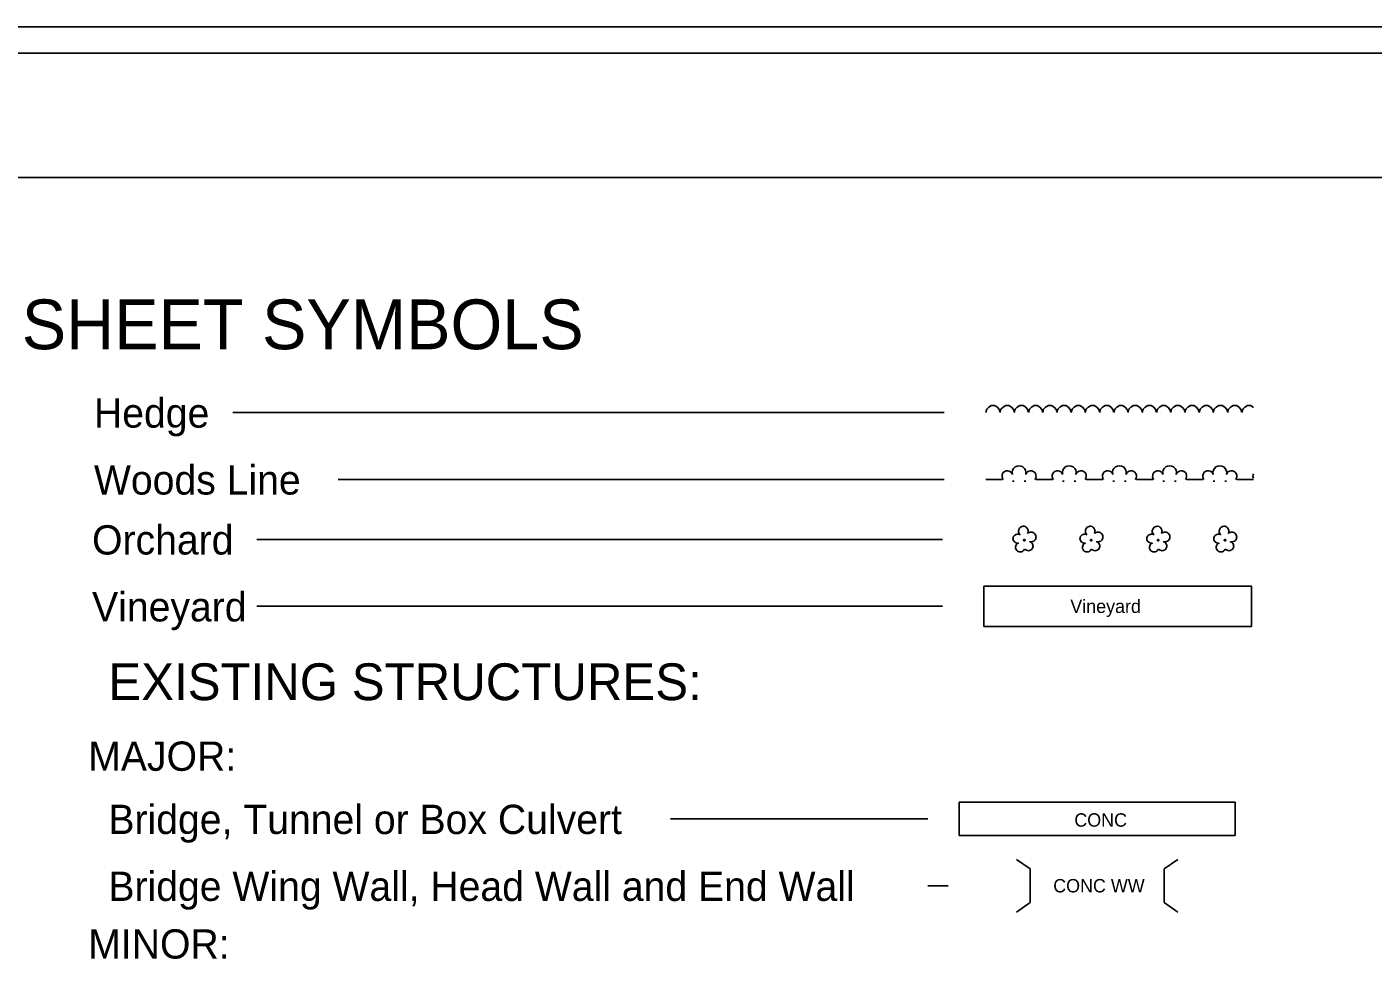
# Model space of a CAD drawing. Extents: x 811137 to 813186, y 647386 to 648494.
# Drawn here: x 812004.1 to 812410, y 648210.2 to 648494 of the extents above; entities that cross this region are included whole.
import ezdxf

# ---------------------------------------------------------------- set-up
doc = ezdxf.new("R2010")
doc.units = 0
for name, color, linetype in [('Default', 7, 'Continuous'), ('Sheet_Plan', 7, 'Continuous'), ('Sheet_Symbology', 7, 'Continuous'), ('z - Construction', 7, 'Continuous')]:
    doc.layers.add(name, color=color, linetype=linetype)

msp = doc.modelspace()

# ---------------------------------------------------------------- linework, layer by layer
at = {"layer": 'Default'}
msp.add_lwpolyline([(812820.63, 648494.02), (811136.63, 648494.02), (811136.63, 647394.02), (812820.63, 647394.02)], close=True, dxfattribs=at)
at = {"layer": 'Sheet_Plan'}
msp.add_line((812803.27, 648448.58), (811178.27, 648448.58), dxfattribs=at)
at = {"layer": 'Sheet_Symbology'}
for p, q in [((812293.25, 648377.76), (812293.56, 648378.72)), ((812293.56, 648378.72), (812294.16, 648379.37)), ((812294.16, 648379.37), (812294.97, 648379.83)), ((812294.97, 648379.83), (812295.93, 648379.83)), ((812295.93, 648379.83), (812296.74, 648379.32)), ((812296.74, 648379.32), (812297.29, 648378.67)), ((812297.29, 648378.67), (812297.49, 648377.81)), ((812297.54, 648377.76), (812297.84, 648378.72)), ((812297.84, 648378.72), (812298.45, 648379.37)), ((812298.45, 648379.37), (812299.26, 648379.83)), ((812299.26, 648379.83), (812300.22, 648379.83)), ((812300.22, 648379.83), (812301.02, 648379.32)), ((812301.02, 648379.32), (812301.58, 648378.67)), ((812301.58, 648378.67), (812301.78, 648377.81)), ((812301.83, 648377.76), (812302.13, 648378.72)), ((812302.13, 648378.72), (812302.74, 648379.37)), ((812302.74, 648379.37), (812303.55, 648379.83)), ((812303.55, 648379.83), (812304.5, 648379.83)), ((812304.5, 648379.83), (812305.31, 648379.32)), ((812305.31, 648379.32), (812305.87, 648378.67)), ((812305.87, 648378.67), (812306.07, 648377.81)), ((812306.12, 648377.76), (812306.42, 648378.72)), ((812306.42, 648378.72), (812307.03, 648379.37)), ((812307.03, 648379.37), (812307.83, 648379.83)), ((812307.83, 648379.83), (812308.79, 648379.83)), ((812308.79, 648379.83), (812309.6, 648379.32)), ((812309.6, 648379.32), (812310.15, 648378.67)), ((812310.15, 648378.67), (812310.36, 648377.81)), ((812310.41, 648377.76), (812310.71, 648378.72)), ((812310.71, 648378.72), (812311.31, 648379.37)), ((812311.31, 648379.37), (812312.12, 648379.83)), ((812312.12, 648379.83), (812313.08, 648379.83)), ((812313.08, 648379.83), (812313.89, 648379.32)), ((812313.89, 648379.32), (812314.44, 648378.67)), ((812314.44, 648378.67), (812314.64, 648377.81)), ((812314.69, 648377.76), (812315, 648378.72)), ((812315, 648378.72), (812315.6, 648379.37)), ((812315.6, 648379.37), (812316.41, 648379.83)), ((812316.41, 648379.83), (812317.37, 648379.83)), ((812317.37, 648379.83), (812318.17, 648379.32)), ((812318.17, 648379.32), (812318.73, 648378.67)), ((812318.73, 648378.67), (812318.93, 648377.81)), ((812318.98, 648377.76), (812319.28, 648378.72)), ((812319.28, 648378.72), (812319.89, 648379.37)), ((812319.89, 648379.37), (812320.7, 648379.83)), ((812320.7, 648379.83), (812321.66, 648379.83)), ((812321.66, 648379.83), (812322.46, 648379.32)), ((812322.46, 648379.32), (812323.02, 648378.67)), ((812323.02, 648378.67), (812323.22, 648377.81)), ((812323.27, 648377.76), (812323.57, 648378.72)), ((812323.57, 648378.72), (812324.18, 648379.37)), ((812324.18, 648379.37), (812324.99, 648379.83)), ((812324.99, 648379.83), (812325.94, 648379.83)), ((812325.94, 648379.83), (812326.75, 648379.32)), ((812326.75, 648379.32), (812327.31, 648378.67)), ((812327.31, 648378.67), (812327.51, 648377.81)), ((812327.56, 648377.76), (812327.86, 648378.72)), ((812327.86, 648378.72), (812328.47, 648379.37)), ((812328.47, 648379.37), (812329.27, 648379.83)), ((812329.27, 648379.83), (812330.23, 648379.83)), ((812330.23, 648379.83), (812331.04, 648379.32)), ((812331.04, 648379.32), (812331.59, 648378.67)), ((812331.59, 648378.67), (812331.8, 648377.81)), ((812331.85, 648377.76), (812332.15, 648378.72)), ((812332.15, 648378.72), (812332.75, 648379.37)), ((812332.75, 648379.37), (812333.56, 648379.83)), ((812333.56, 648379.83), (812334.52, 648379.83)), ((812334.52, 648379.83), (812335.33, 648379.32)), ((812335.33, 648379.32), (812335.88, 648378.67)), ((812335.88, 648378.67), (812336.08, 648377.81)), ((812336.13, 648377.76), (812336.44, 648378.72)), ((812336.44, 648378.72), (812337.04, 648379.37)), ((812337.04, 648379.37), (812337.85, 648379.83)), ((812337.85, 648379.83), (812338.81, 648379.83)), ((812338.81, 648379.83), (812339.61, 648379.32)), ((812339.61, 648379.32), (812340.17, 648378.67)), ((812340.17, 648378.67), (812340.37, 648377.81)), ((812340.42, 648377.76), (812340.72, 648378.72)), ((812340.72, 648378.72), (812341.33, 648379.37)), ((812341.33, 648379.37), (812342.14, 648379.83)), ((812342.14, 648379.83), (812343.1, 648379.83)), ((812343.1, 648379.83), (812343.9, 648379.32)), ((812343.9, 648379.32), (812344.46, 648378.67)), ((812344.46, 648378.67), (812344.66, 648377.81)), ((812344.71, 648377.76), (812345.01, 648378.72)), ((812345.01, 648378.72), (812345.62, 648379.37)), ((812345.62, 648379.37), (812346.43, 648379.83)), ((812346.43, 648379.83), (812347.38, 648379.83)), ((812347.38, 648379.83), (812348.19, 648379.32)), ((812348.19, 648379.32), (812348.75, 648378.67)), ((812348.75, 648378.67), (812348.95, 648377.81)), ((812349, 648377.76), (812349.3, 648378.72)), ((812349.3, 648378.72), (812349.91, 648379.37)), ((812349.91, 648379.37), (812350.71, 648379.83)), ((812350.71, 648379.83), (812351.67, 648379.83)), ((812351.67, 648379.83), (812352.48, 648379.32)), ((812352.48, 648379.32), (812353.03, 648378.67)), ((812353.03, 648378.67), (812353.24, 648377.81)), ((812353.29, 648377.76), (812353.59, 648378.72)), ((812353.59, 648378.72), (812354.19, 648379.37)), ((812354.19, 648379.37), (812355, 648379.83)), ((812355, 648379.83), (812355.96, 648379.83)), ((812355.96, 648379.83), (812356.77, 648379.32)), ((812356.77, 648379.32), (812357.32, 648378.67)), ((812357.32, 648378.67), (812357.52, 648377.81)), ((812357.57, 648377.76), (812357.88, 648378.72)), ((812357.88, 648378.72), (812358.48, 648379.37)), ((812358.48, 648379.37), (812359.29, 648379.83)), ((812359.29, 648379.83), (812360.25, 648379.83)), ((812360.25, 648379.83), (812361.05, 648379.32)), ((812361.05, 648379.32), (812361.61, 648378.67)), ((812361.61, 648378.67), (812361.81, 648377.81)), ((812361.86, 648377.76), (812362.16, 648378.72)), ((812362.16, 648378.72), (812362.77, 648379.37)), ((812362.77, 648379.37), (812363.58, 648379.83)), ((812363.58, 648379.83), (812364.54, 648379.83)), ((812364.54, 648379.83), (812365.34, 648379.32)), ((812365.34, 648379.32), (812365.9, 648378.67)), ((812365.9, 648378.67), (812366.1, 648377.81)), ((812366.15, 648377.76), (812366.45, 648378.72)), ((812366.45, 648378.72), (812367.06, 648379.37)), ((812367.06, 648379.37), (812367.87, 648379.83)), ((812367.87, 648379.83), (812368.82, 648379.83)), ((812368.82, 648379.83), (812369.63, 648379.32)), ((812369.63, 648379.32), (812370.19, 648378.67)), ((812370.19, 648378.67), (812370.39, 648377.81)), ((812370.44, 648377.76), (812370.74, 648378.72)), ((812370.74, 648378.72), (812371.35, 648379.37)), ((812371.35, 648379.37), (812372.15, 648379.83)), ((812372.15, 648379.83), (812373.11, 648379.83)), ((812373.11, 648379.83), (812373.92, 648379.32)), ((812373.92, 648379.32), (812373.97, 648379.27)), ((812280.75, 648377.76), (812066.16, 648377.76)), ((812280.75, 648357.58), (812098.01, 648357.58)), ((812293.25, 648357.58), (812298.3, 648357.58)), ((812301.28, 648357.08), (812301.78, 648357.08)), ((812304.81, 648357.08), (812305.31, 648357.08)), ((812308.39, 648357.58), (812313.43, 648357.58)), ((812316.41, 648357.08), (812316.91, 648357.08)), ((812319.94, 648357.08), (812320.45, 648357.08)), ((812323.52, 648357.58), (812328.57, 648357.58)), ((812331.54, 648357.08), (812332.05, 648357.08)), ((812335.07, 648357.08), (812335.58, 648357.08)), ((812338.66, 648357.58), (812343.7, 648357.58)), ((812346.68, 648357.08), (812347.18, 648357.08)), ((812350.21, 648357.08), (812350.71, 648357.08)), ((812353.79, 648357.58), (812358.84, 648357.58)), ((812361.81, 648357.08), (812362.32, 648357.08)), ((812365.34, 648357.08), (812365.85, 648357.08)), ((812368.92, 648357.58), (812373.97, 648357.58)), ((812280.18, 648339.49), (812073.41, 648339.49)), ((812280.18, 648319.31), (812073.41, 648319.31)), ((812275.83, 648255.24), (812198.17, 648255.24)), ((812302.51, 648242.99), (812306.65, 648240.11)), ((812351.14, 648242.99), (812347.01, 648240.11)), ((812306.65, 648240.11), (812306.65, 648230.02)), ((812347.01, 648240.11), (812347.01, 648230.02)), ((812275.83, 648235.06), (812281.87, 648235.06)), ((812302.51, 648227.13), (812306.65, 648230.02)), ((812351.14, 648227.13), (812347.01, 648230.02))]:
    msp.add_line(p, q, dxfattribs=at)
for points in [[(812305.85, 648341.26), (812306, 648341.56), (812306.05, 648341.86), (812306, 648342.17), (812305.95, 648342.47), (812305.8, 648342.72), (812305.65, 648342.97), (812305.4, 648343.18), (812305.14, 648343.33), (812304.79, 648343.43), (812304.54, 648343.43), (812304.24, 648343.38), (812303.93, 648343.28), (812303.68, 648343.13), (812303.43, 648342.92), (812303.28, 648342.62), (812303.18, 648342.37), (812303.13, 648342.07), (812303.13, 648341.76), (812303.18, 648341.46), (812303.33, 648341.21), (812303.53, 648340.91), (812303.28, 648341.06), (812302.97, 648341.11), (812302.67, 648341.11), (812302.42, 648341.01), (812302.17, 648340.91), (812301.92, 648340.7), (812301.71, 648340.5), (812301.56, 648340.25), (812301.51, 648340), (812301.46, 648339.64), (812301.51, 648339.39), (812301.61, 648339.14), (812301.81, 648338.89), (812301.97, 648338.69), (812302.22, 648338.53), (812302.52, 648338.38), (812302.77, 648338.33), (812303.08, 648338.33), (812302.82, 648338.23), (812302.57, 648338.03), (812302.42, 648337.83), (812302.32, 648337.53), (812302.22, 648337.22), (812302.22, 648336.97), (812302.27, 648336.67), (812302.42, 648336.42), (812302.57, 648336.16), (812302.77, 648335.96), (812303.03, 648335.81), (812303.28, 648335.71), (812303.58, 648335.71), (812303.88, 648335.71), (812304.14, 648335.76), (812304.39, 648335.96), (812304.64, 648336.11), (812304.89, 648336.57)], [(812326.03, 648341.26), (812326.18, 648341.56), (812326.23, 648341.86), (812326.18, 648342.17), (812326.13, 648342.47), (812325.98, 648342.72), (812325.83, 648342.97), (812325.58, 648343.18), (812325.32, 648343.33), (812324.97, 648343.43), (812324.72, 648343.43), (812324.41, 648343.38), (812324.11, 648343.28), (812323.86, 648343.13), (812323.61, 648342.92), (812323.46, 648342.62), (812323.36, 648342.37), (812323.31, 648342.07), (812323.31, 648341.76), (812323.36, 648341.46), (812323.51, 648341.21), (812323.71, 648340.91), (812323.46, 648341.06), (812323.15, 648341.11), (812322.85, 648341.11), (812322.6, 648341.01), (812322.35, 648340.91), (812322.09, 648340.7), (812321.89, 648340.5), (812321.74, 648340.25), (812321.69, 648340), (812321.64, 648339.64), (812321.69, 648339.39), (812321.79, 648339.14), (812321.99, 648338.89), (812322.14, 648338.69), (812322.4, 648338.53), (812322.7, 648338.38), (812322.95, 648338.33), (812323.25, 648338.33), (812323, 648338.23), (812322.75, 648338.03), (812322.6, 648337.83), (812322.5, 648337.53), (812322.4, 648337.22), (812322.4, 648336.97), (812322.45, 648336.67), (812322.6, 648336.42), (812322.75, 648336.16), (812322.95, 648335.96), (812323.2, 648335.81), (812323.46, 648335.71), (812323.76, 648335.71), (812324.06, 648335.71), (812324.31, 648335.76), (812324.57, 648335.96), (812324.82, 648336.11), (812325.07, 648336.57)], [(812346.21, 648341.26), (812346.36, 648341.56), (812346.41, 648341.86), (812346.36, 648342.17), (812346.31, 648342.47), (812346.16, 648342.72), (812346.01, 648342.97), (812345.75, 648343.18), (812345.5, 648343.33), (812345.15, 648343.43), (812344.9, 648343.43), (812344.59, 648343.38), (812344.29, 648343.28), (812344.04, 648343.13), (812343.79, 648342.92), (812343.64, 648342.62), (812343.53, 648342.37), (812343.48, 648342.07), (812343.48, 648341.76), (812343.53, 648341.46), (812343.69, 648341.21), (812343.89, 648340.91), (812343.64, 648341.06), (812343.33, 648341.11), (812343.03, 648341.11), (812342.78, 648341.01), (812342.53, 648340.91), (812342.27, 648340.7), (812342.07, 648340.5), (812341.92, 648340.25), (812341.87, 648340), (812341.82, 648339.64), (812341.87, 648339.39), (812341.97, 648339.14), (812342.17, 648338.89), (812342.32, 648338.69), (812342.58, 648338.53), (812342.88, 648338.38), (812343.13, 648338.33), (812343.43, 648338.33), (812343.18, 648338.23), (812342.93, 648338.03), (812342.78, 648337.83), (812342.68, 648337.53), (812342.58, 648337.22), (812342.58, 648336.97), (812342.63, 648336.67), (812342.78, 648336.42), (812342.93, 648336.16), (812343.13, 648335.96), (812343.38, 648335.81), (812343.64, 648335.71), (812343.94, 648335.71), (812344.24, 648335.71), (812344.49, 648335.76), (812344.74, 648335.96), (812345, 648336.11), (812345.25, 648336.57)], [(812366.39, 648341.26), (812366.54, 648341.56), (812366.59, 648341.86), (812366.54, 648342.17), (812366.49, 648342.47), (812366.34, 648342.72), (812366.18, 648342.97), (812365.93, 648343.18), (812365.68, 648343.33), (812365.33, 648343.43), (812365.08, 648343.43), (812364.77, 648343.38), (812364.47, 648343.28), (812364.22, 648343.13), (812363.97, 648342.92), (812363.81, 648342.62), (812363.71, 648342.37), (812363.66, 648342.07), (812363.66, 648341.76), (812363.71, 648341.46), (812363.86, 648341.21), (812364.07, 648340.91), (812363.81, 648341.06), (812363.51, 648341.11), (812363.21, 648341.11), (812362.96, 648341.01), (812362.7, 648340.91), (812362.45, 648340.7), (812362.25, 648340.5), (812362.1, 648340.25), (812362.05, 648340), (812362, 648339.64), (812362.05, 648339.39), (812362.15, 648339.14), (812362.35, 648338.89), (812362.5, 648338.69), (812362.75, 648338.53), (812363.06, 648338.38), (812363.31, 648338.33), (812363.61, 648338.33), (812363.36, 648338.23), (812363.11, 648338.03), (812362.96, 648337.83), (812362.86, 648337.53), (812362.75, 648337.22), (812362.75, 648336.97), (812362.8, 648336.67), (812362.96, 648336.42), (812363.11, 648336.16), (812363.31, 648335.96), (812363.56, 648335.81), (812363.81, 648335.71), (812364.12, 648335.71), (812364.42, 648335.71), (812364.67, 648335.76), (812364.92, 648335.96), (812365.18, 648336.11), (812365.43, 648336.57)], [(812304.99, 648339.49), (812304.84, 648339.49), (812304.74, 648339.44), (812304.64, 648339.39), (812304.64, 648339.24), (812304.64, 648339.14), (812304.74, 648339.04), (812304.89, 648339.04), (812304.99, 648339.04), (812305.09, 648339.14), (812305.14, 648339.29), (812305.09, 648339.39), (812304.99, 648339.49)], [(812304.89, 648336.57), (812305.5, 648336.21), (812305.8, 648336.11), (812306.1, 648336.06), (812306.41, 648336.11), (812306.66, 648336.21), (812306.91, 648336.37), (812307.16, 648336.57), (812307.31, 648336.82), (812307.41, 648337.07), (812307.52, 648337.37), (812307.46, 648337.68), (812307.41, 648337.98), (812307.21, 648338.28), (812307.06, 648338.48), (812306.81, 648338.64), (812306.51, 648338.79), (812306.81, 648338.74), (812307.16, 648338.74), (812307.41, 648338.84), (812307.72, 648338.99), (812307.97, 648339.14), (812308.17, 648339.39), (812308.32, 648339.69), (812308.37, 648340), (812308.42, 648340.3), (812308.37, 648340.6), (812308.27, 648340.91), (812308.07, 648341.16), (812307.82, 648341.41), (812307.57, 648341.56), (812307.26, 648341.66), (812306.96, 648341.71), (812306.66, 648341.71), (812306.35, 648341.61), (812306.1, 648341.46), (812305.85, 648341.26)], [(812325.17, 648339.49), (812325.02, 648339.49), (812324.92, 648339.44), (812324.82, 648339.39), (812324.82, 648339.24), (812324.82, 648339.14), (812324.92, 648339.04), (812325.07, 648339.04), (812325.17, 648339.04), (812325.27, 648339.14), (812325.32, 648339.29), (812325.27, 648339.39), (812325.17, 648339.49)], [(812325.07, 648336.57), (812325.68, 648336.21), (812325.98, 648336.11), (812326.28, 648336.06), (812326.58, 648336.11), (812326.84, 648336.21), (812327.09, 648336.37), (812327.34, 648336.57), (812327.49, 648336.82), (812327.59, 648337.07), (812327.69, 648337.37), (812327.64, 648337.68), (812327.59, 648337.98), (812327.39, 648338.28), (812327.24, 648338.48), (812326.99, 648338.64), (812326.69, 648338.79), (812326.99, 648338.74), (812327.34, 648338.74), (812327.59, 648338.84), (812327.9, 648338.99), (812328.15, 648339.14), (812328.35, 648339.39), (812328.5, 648339.69), (812328.55, 648340), (812328.6, 648340.3), (812328.55, 648340.6), (812328.45, 648340.91), (812328.25, 648341.16), (812328, 648341.41), (812327.74, 648341.56), (812327.44, 648341.66), (812327.14, 648341.71), (812326.84, 648341.71), (812326.53, 648341.61), (812326.28, 648341.46), (812326.03, 648341.26)], [(812345.35, 648339.49), (812345.2, 648339.49), (812345.1, 648339.44), (812345, 648339.39), (812345, 648339.24), (812345, 648339.14), (812345.1, 648339.04), (812345.25, 648339.04), (812345.35, 648339.04), (812345.45, 648339.14), (812345.5, 648339.29), (812345.45, 648339.39), (812345.35, 648339.49)], [(812345.25, 648336.57), (812345.85, 648336.21), (812346.16, 648336.11), (812346.46, 648336.06), (812346.76, 648336.11), (812347.02, 648336.21), (812347.27, 648336.37), (812347.52, 648336.57), (812347.67, 648336.82), (812347.77, 648337.07), (812347.87, 648337.37), (812347.82, 648337.68), (812347.77, 648337.98), (812347.57, 648338.28), (812347.42, 648338.48), (812347.17, 648338.64), (812346.86, 648338.79), (812347.17, 648338.74), (812347.52, 648338.74), (812347.77, 648338.84), (812348.07, 648338.99), (812348.33, 648339.14), (812348.53, 648339.39), (812348.68, 648339.69), (812348.73, 648340), (812348.78, 648340.3), (812348.73, 648340.6), (812348.63, 648340.91), (812348.43, 648341.16), (812348.18, 648341.41), (812347.92, 648341.56), (812347.62, 648341.66), (812347.32, 648341.71), (812347.02, 648341.71), (812346.71, 648341.61), (812346.46, 648341.46), (812346.21, 648341.26)], [(812365.53, 648339.49), (812365.38, 648339.49), (812365.28, 648339.44), (812365.18, 648339.39), (812365.18, 648339.24), (812365.18, 648339.14), (812365.28, 648339.04), (812365.43, 648339.04), (812365.53, 648339.04), (812365.63, 648339.14), (812365.68, 648339.29), (812365.63, 648339.39), (812365.53, 648339.49)], [(812365.43, 648336.57), (812366.03, 648336.21), (812366.34, 648336.11), (812366.64, 648336.06), (812366.94, 648336.11), (812367.19, 648336.21), (812367.45, 648336.37), (812367.7, 648336.57), (812367.85, 648336.82), (812367.95, 648337.07), (812368.05, 648337.37), (812368, 648337.68), (812367.95, 648337.98), (812367.75, 648338.28), (812367.6, 648338.48), (812367.35, 648338.64), (812367.04, 648338.79), (812367.35, 648338.74), (812367.7, 648338.74), (812367.95, 648338.84), (812368.25, 648338.99), (812368.51, 648339.14), (812368.71, 648339.39), (812368.86, 648339.69), (812368.91, 648340), (812368.96, 648340.3), (812368.91, 648340.6), (812368.81, 648340.91), (812368.61, 648341.16), (812368.35, 648341.41), (812368.1, 648341.56), (812367.8, 648341.66), (812367.5, 648341.71), (812367.19, 648341.71), (812366.89, 648341.61), (812366.64, 648341.46), (812366.39, 648341.26)], [(812292.68, 648325.37), (812373.4, 648325.37), (812373.4, 648313.26), (812292.68, 648313.26), (812292.68, 648325.37)], [(812285.21, 648260.29), (812368.45, 648260.29), (812368.45, 648250.2), (812285.21, 648250.2), (812285.21, 648260.29)]]:
    msp.add_lwpolyline(points, dxfattribs=at)
for centre, radius, start, end in [((812299.76, 648358.6), 1.6, 18.435, 219.2315), ((812303.29, 648359.61), 2.08, 345.9638, 194.0362), ((812306.82, 648358.6), 1.6, 320.7685, 161.5651), ((812314.89, 648358.6), 1.6, 18.435, 219.2315), ((812318.42, 648359.61), 2.08, 345.9638, 194.0362), ((812321.96, 648358.6), 1.6, 320.7685, 161.5651), ((812330.03, 648358.6), 1.6, 18.435, 219.2315), ((812333.56, 648359.61), 2.08, 345.9638, 194.0362), ((812337.09, 648358.6), 1.6, 320.7685, 161.5651), ((812345.16, 648358.6), 1.6, 18.435, 219.2315), ((812348.69, 648359.61), 2.08, 345.9638, 194.0362), ((812352.22, 648358.6), 1.6, 320.7685, 161.5651), ((812360.3, 648358.6), 1.6, 18.435, 219.2315), ((812363.83, 648359.61), 2.08, 345.9638, 194.0362), ((812367.36, 648358.6), 1.6, 320.7685, 161.5651), ((812375.43, 648358.6), 1.6, 156.251, 203.749)]:
    msp.add_arc(centre, radius, start, end, dxfattribs=at)
at = {"layer": 'z - Construction'}
msp.add_line((812840.77, 648486.08), (811140.78, 648486.08), dxfattribs=at)

# ---------------------------------------------------------------- texts
at = {"layer": 'Sheet_Symbology'}
for s, height, p in [('CONVENTIONAL  PLAN SHEET SYMBOLS', 15, (811775.17, 648396.83)), ('Hedge', 8.828, (812024.32, 648373.19)), ('Woods Line', 8.828, (812024.32, 648353.01)), ('Orchard', 8.828, (812023.75, 648334.93)), ('Vineyard', 8.828, (812023.75, 648314.75)), ('EXISTING STRUCTURES:', 11.0983, (812028.67, 648291.01)), ('MAJOR:', 8.828, (812022.6, 648269.71)), ('Bridge, Tunnel or Box Culvert', 8.8282, (812028.67, 648250.65)), ('CONC', 4.036, (812319.95, 648252.86)), ('Bridge Wing Wall, Head Wall and End Wall', 8.8282, (812028.67, 648230.47)), ('MINOR:', 8.828, (812022.6, 648213.08))]:
    msp.add_text(s, height=height, dxfattribs=at).set_placement(p)
for s, p in [('Vineyard', (812318.74, 648317.3)), ('CONC WW', (812313.59, 648233.04))]:
    msp.add_text(s, height=4.036, rotation=0, dxfattribs=at).set_placement(p)

doc.saveas('drawing.dxf')
